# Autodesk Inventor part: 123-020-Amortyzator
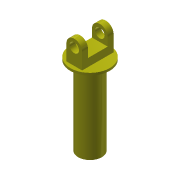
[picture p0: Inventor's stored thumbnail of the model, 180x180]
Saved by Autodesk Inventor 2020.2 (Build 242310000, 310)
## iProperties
Created: 2014-12
Part Number: 123-020-Amortyzator
Material: Aluminium 6061
Document SubType Name: Modeling
Designer: F.Stasiak
Density: 2.7 g/cm^3
Appearance: Żółta
Catalog Web Link: www.expertbooks.pl
Manager: www.cadconsulting.pl
Company: Fabian Stasiak CAD Consulting
Author: F.Stasiak
Subject: Zbiór ćwiczeń. Autodesk Inventor 2020. Kurs Professional
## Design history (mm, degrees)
sketch "Szkic1"
  geometry: C1 r 25 at (0, 0); 1 further point
  constraints: 1 centre point, 1 coincident
  dimensions: "d0" = 50 diameter of C1
extrude "Wyciągnięcie proste1" new body sketch "Szkic1" distance "d1" = 3; taper "d2" = 0 deg
sketch "Szkic2"
  geometry: L1 (-10, 20)-(10, 20); L2 (10, 20)-(10, -20); L3 (10, -20)-(-10, -20); L4 (-10, -20)-(-10, 20); L5 (-10, 20)-(10, -20); L6 (10, 20)-(-10, -20); 1 further point
  constraints: 12 end point, 2 midpoint, 2 parallel, 1 horizontal, 1 perpendicular
  dimensions: "d3" = 20 distance of L2.end L3.end; "d4" = 40 distance of L1.end L2.end
extrude "Wyciągnięcie proste2" join sketch "Szkic2" distance "d5" = 30; taper "d6" = 0 deg
sketch "Szkic3"
  geometry: L1 (0, 40)-(0, 0) reference; L2 (0, 40)-(-30, 40) reference; L3 (-30, 0)-(-30, 40) reference; L4 (0, 0)-(-30, 0) reference; L5 (-30, 32.5)-(-10, 32.5); L6 (-10, 32.5)-(-10, 7.5); L7 (-10, 7.5)-(-30, 7.5); L8 (-30, 7.5)-(-30, 32.5); 2 further points
  constraints: 8 end point, 2 midpoint, 2 parallel, 1 horizontal, 1 perpendicular
  dimensions: "d7" = 20 distance of L6.end L7.end; "d8" = 25 distance of L5.end L6.end
extrude "Wyciągnięcie proste3" cut sketch "Szkic3" extent not by distance; stored distance "d9" = 30; taper "d10" = 0 deg
fillet "Zaokrąglenie1" dims "d11" = 10 (= 0.5 x d3)
sketch "Szkic4"
  geometry: L1 (0, 0)-(0, 20) reference; L2 (20, 0)-(0, 0) reference; L3 (20, 0)-(20, 20) reference; C1 r 6 at (10, 20); A1 r 10 centre (10, 20) between (20, 20) and (0, 20) reference; 1 further point
  constraints: 1 centre point, 1 coincident
  dimensions: "d12" = 12 diameter of C1
extrude "Wyciągnięcie proste4" cut sketch "Szkic4" extent not by distance; stored distance "d13" = 30; taper "d14" = 0 deg
sketch "Szkic5"
  geometry: C1 r 12.5 at (0, 0); C2 r 15 at (0, 0); 1 further point
  constraints: 2 centre point, 2 coincident
  dimensions: "d15" = 25 diameter of C1; "d16" = 30 diameter of C2
extrude "Wyciągnięcie proste5" join sketch "Szkic5" distance "d17" = 100; taper "d18" = 0 deg
node "Bryła1"
node "Pętla rzutowana1"
node "Pętla rzutowana2"
